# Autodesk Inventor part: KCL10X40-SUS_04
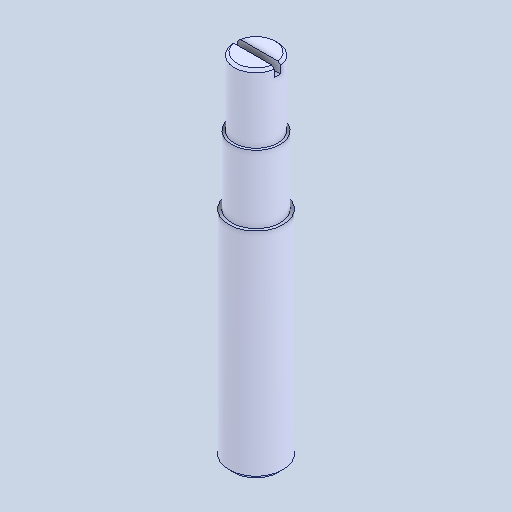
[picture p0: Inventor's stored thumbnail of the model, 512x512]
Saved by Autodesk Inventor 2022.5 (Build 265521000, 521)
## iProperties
Created: 2024-08
Part Number: KCL10X40-SUS_04
Material: 一般
Document SubType Name: Modeling
Designer: ImaoCorp
Density: 1 g/cm^3
Appearance: 既定
Author: ImaoCorp
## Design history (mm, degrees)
feature "KCL10X40-SUS_04"
node "ソリッド1"
